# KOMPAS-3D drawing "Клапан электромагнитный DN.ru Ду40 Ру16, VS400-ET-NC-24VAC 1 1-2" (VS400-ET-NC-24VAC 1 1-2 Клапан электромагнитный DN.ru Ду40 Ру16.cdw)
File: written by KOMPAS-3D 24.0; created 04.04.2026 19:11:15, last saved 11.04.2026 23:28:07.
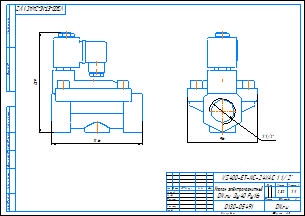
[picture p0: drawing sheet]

Document properties: c3d_UniqueCompID: ef56311e-7521-43dc-8291-0e6108b3d81d; Обозначение: VS400-ET-NC-220VAC 1; Наименование: Клапан электромагнитный DN.ru Ду25 Ру16; Автор: artio; Класс точности: c; Знак неуказанной шероховатости: Шероховатость не задана; Рассекать на разрезах: Да; c3d_UniqueCompID: ef56311e-7521-43dc-8291-0e6108b3d81d; Обозначение: VS400-ET-NC-220VAC 1-2; Наименование: Клапан электромагнитный DN.ru Ду15 Ру16; Автор: artio; Класс точности: c; Знак неуказанной шероховатости: Шероховатость не задана; Рассекать на разрезах: Да; c3d_UniqueCompID: ef56311e-7521-43dc-8291-0e6108b3d81d; Обозначение: VS400-ET-NC-220VAC 3-4; Наименование: Клапан электромагнитный DN.ru Ду20 Ру16; Автор: artio; Класс точности: c; Знак неуказанной шероховатости: Шероховатость не задана; Рассекать на разрезах: Да; c3d_UniqueCompID: ef56311e-7521-43dc-8291-0e6108b3d81d; Обозначение: VS400-ET-NC-220VAC 1 1-4; Наименование: Клапан электромагнитный DN.ru Ду32 Ру16; Автор: artio; Класс точности: c; Знак неуказанной шероховатости: Шероховатость не задана; Рассекать на разрезах: Да; c3d_UniqueCompID: ef56311e-7521-43dc-8291-0e6108b3d81d; Обозначение: VS400-ET-NC-220VAC 3-8; Наименование: Клапан электромагнитный DN.ru Ду10 Ру16; Автор: artio; Класс точности: c; Знак неуказанной шероховатости: Шероховатость не задана; Рассекать на разрезах: Да; c3d_UniqueCompID: ef56311e-7521-43dc-8291-0e6108b3d81d; Обозначение: VS400-ET-NC-220VAC 1 1-2; Наименование: Клапан электромагнитный DN.ru Ду40 Ру16; Автор: artio; Класс точности: c; Знак неуказанной шероховатости: Шероховатость не задана; Рассекать на разрезах: Да; Автор: artio; Форматы листов документа: A3; Полное имя файла: VS400-ET-NC-24VAC 1 1-2 Клапан электромагнитный DN.ru Ду40 Ру16.m3d; Масса: 2.321; Наименование: Клапан электромагнитный DN.ru Ду40 Ру16; Количество листов документа: 1; Примечание: D130-05491

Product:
- Body: Тело 1  | qty 1
    Масса: 4.144257
- Part/product: Клапан электромагнитный DN.ru Ду40 Ру16  | designation VS400-ET-NC-24VAC 1 1-2
    Масса: 2.321
    Раздел спецификации: Прочие изделия
    Примечание: D130-05491
    additional columns: ef56311e-7521-43dc-8291-0e6108b3d81d; VS400-ET-NC-220VAC 1 1-2; artio; c; Шероховатость не задана; Да

Views: Вид 1, Спереди
Referenced files in C:\Users\artio\OneDrive\Рабочий стол\Клапан электромагнитный DN.ru\VS400-ET-NC\VS400-ET-NC-24VDC\: VS400-ET-NC-24VDC 3-8 Клапан электромагнитный DN.ru Ду10 Ру16.m3d
Referenced files in C:\Users\artio\OneDrive\Рабочий стол\Клапан электромагнитный DN.ru\VS400\VS400-ET-NC\VS400-ET-NC-24VAC\Ду40\: VS400-ET-NC-24VAC 1 1-2 Клапан электромагнитный DN.ru Ду40 Ру16.m3d
Referenced files in C:\Users\artio\OneDrive\Рабочий стол\Клапан электромагнитный DN.ru\VS400-ET-NC\: VS400-ET-NC-24VDC 3-8 Клапан электромагнитный DN.ru Ду10 Ру16.cdw
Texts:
  VS400-ET-NC-24VAC 1 1-2
  Клапан электромагнитный
  DN.ru Ду40 Ру16
  VS400-ET-NC-24VAC 1 1/2"
  VS400-ET-NC-24VAC 1 1/2"-
  Клапан электромагнитный DN.ru Ду40 Ру16
  VS400-ET-NC-24VAC 1 1-2 Клапан электромагнитный DN.ru Ду40 Ру16
Dimensions and other numbers on the sheet: 0; 3; 2; 4; 96; 1 1/2"; 1:1; 1; 2,32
